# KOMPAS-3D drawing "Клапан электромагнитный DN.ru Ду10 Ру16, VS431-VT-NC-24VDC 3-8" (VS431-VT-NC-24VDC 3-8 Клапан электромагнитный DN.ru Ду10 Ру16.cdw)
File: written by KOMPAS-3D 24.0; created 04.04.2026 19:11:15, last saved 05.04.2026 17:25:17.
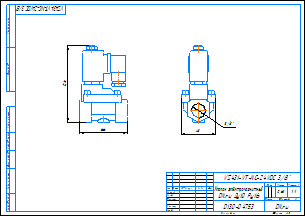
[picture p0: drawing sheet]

Document properties: c3d_UniqueCompID: ef56311e-7521-43dc-8291-0e6108b3d81d; Обозначение: VS400-ET-NC-220VAC 3-8; Наименование: Клапан электромагнитный DN.ru Ду10 Ру16; Автор: artio; Класс точности: c; Знак неуказанной шероховатости: Шероховатость не задана; Рассекать на разрезах: Да; Автор: artio; Форматы листов документа: A3; Полное имя файла: VS431-VT-NC-24VDC 3-8 Клапан электромагнитный DN.ru Ду10 Ру16.m3d; Масса: 0.62; Наименование: Клапан электромагнитный DN.ru Ду10 Ру16; Количество листов документа: 1; Примечание: D130-04753

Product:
- Body: Тело 1  | qty 1
    Масса: 1.030062
- Part/product: Клапан электромагнитный DN.ru Ду10 Ру16  | designation VS431-VT-NC-24VDC 3-8
    Масса: 0.62
    Раздел спецификации: Прочие изделия
    Примечание: D130-04753
    additional columns: ef56311e-7521-43dc-8291-0e6108b3d81d; VS400-ET-NC-220VAC 3-8; artio; c; Шероховатость не задана; Да

Views: Вид 1, Спереди, Проекционный вид 2
Referenced files in C:\Users\artio\OneDrive\Рабочий стол\Клапан электромагнитный DN.ru\VS400-ET-NC\VS400-ET-NC-24VDC\: VS400-ET-NC-24VDC 3-8 Клапан электромагнитный DN.ru Ду10 Ру16.m3d
Referenced files in C:\Users\artio\OneDrive\Рабочий стол\Клапан электромагнитный DN.ru\VS431\VS431-VT-NC\VS431-VT-NC-24VDC\Ду10\: VS431-VT-NC-24VDC 3-8 Клапан электромагнитный DN.ru Ду10 Ру16.m3d
Referenced files in C:\Users\artio\OneDrive\Рабочий стол\Клапан электромагнитный DN.ru\VS400-VT-NC\VS400-VT-NC-24VDC\: VS400-VT-NC-24VDC 3-8 Клапан электромагнитный DN.ru Ду10 Ру16.cdw
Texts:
  VS431-VT-NC-24VDC 3-8
  Клапан электромагнитный
  DN.ru Ду10 Ру16
  VS431-VT-NC-24VDC 3/8"
  VS431-VT-NC-24VDC 3/8"-
  Клапан электромагнитный DN.ru Ду10 Ру16
  VS431-VT-NC-24VDC 3-8 Клапан электромагнитный DN.ru Ду10 Ру16
Dimensions and other numbers on the sheet: 0; 3; 2; 4; 48; 3/8"; 66; 106; 1:1; 1; 0,62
